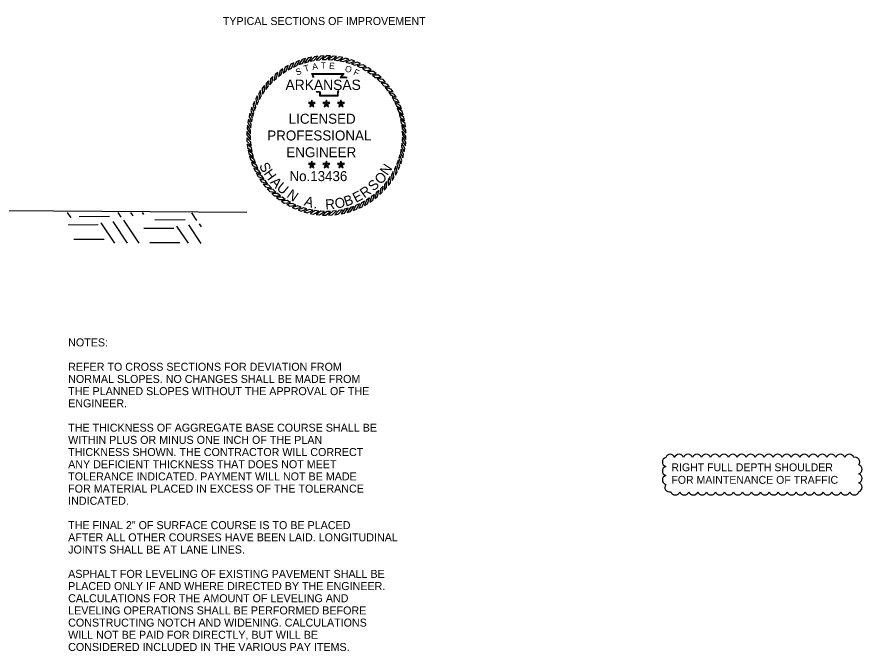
# Model space of a CAD drawing. Extents: x 1398183 to 1398373, y 1967240 to 1968889.
# Drawn here: x 1398305.8 to 1398369.1, y 1967753.9 to 1967801.4 of the extents above; entities that cross this region are included whole.
import ezdxf

# ---------------------------------------------------------------- set-up
doc = ezdxf.new("R2010")
doc.units = 0
for name, color, linetype in [('1', 7, 'Continuous'), ('19', 7, 'Continuous'), ('42', 7, 'Continuous'), ('9', 7, 'Continuous'), ('G-ANNO-SYMB', 7, 'Continuous')]:
    doc.layers.add(name, color=color, linetype=linetype)

msp = doc.modelspace()

# ---------------------------------------------------------------- linework, layer by layer
at = {"layer": '19'}
msp.add_lwpolyline([(1398257.039, 1967783.694), (1398271.783, 1967778.793), (1398285.898, 1967784.503), (1398294.031, 1967786.983), (1398323.027, 1967786.767)], dxfattribs=at)
for centre, radius, start, end in [((1398354.74, 1967768.294), 0.352, 17.5, 162.5), ((1398355.41, 1967768.294), 0.352, 17.5, 162.5), ((1398356.081, 1967768.294), 0.352, 17.5, 162.5), ((1398356.752, 1967768.294), 0.352, 17.5, 162.5), ((1398357.422, 1967768.294), 0.352, 17.5, 162.5), ((1398358.093, 1967768.294), 0.352, 17.5, 162.5), ((1398358.764, 1967768.294), 0.352, 17.5, 162.5), ((1398359.434, 1967768.294), 0.352, 17.5, 162.5), ((1398360.105, 1967768.294), 0.352, 17.5, 162.5), ((1398360.776, 1967768.294), 0.352, 17.5, 162.5), ((1398361.446, 1967768.294), 0.352, 17.5, 162.5), ((1398362.117, 1967768.294), 0.352, 17.5, 162.5), ((1398362.788, 1967768.294), 0.352, 17.5, 162.5), ((1398363.459, 1967768.294), 0.352, 17.5, 162.5), ((1398364.129, 1967768.294), 0.352, 17.5, 162.5), ((1398364.8, 1967768.294), 0.352, 17.5, 162.5), ((1398365.471, 1967768.294), 0.352, 17.5, 162.5), ((1398366.141, 1967768.294), 0.352, 17.5, 162.5), ((1398366.812, 1967768.294), 0.352, 17.5, 162.5), ((1398367.483, 1967768.294), 0.352, 17.5, 162.5), ((1398368.153, 1967768.294), 0.352, 17.5, 162.5), ((1398354.51, 1967768.065), 0.352, 107.5, 252.5), ((1398368.594, 1967768.065), 0.351, 322.43874, 107.43874), ((1398354.51, 1967767.394), 0.352, 107.5, 252.5), ((1398368.767, 1967767.515), 0.352, 287.5, 72.5), ((1398354.51, 1967766.723), 0.352, 107.5, 252.5), ((1398368.767, 1967766.845), 0.352, 287.5, 72.5), ((1398354.683, 1967766.174), 0.351, 142.43874, 287.43874), ((1398368.767, 1967766.174), 0.352, 287.5, 72.5), ((1398355.123, 1967765.944), 0.352, 197.5, 342.5), ((1398355.794, 1967765.944), 0.352, 197.5, 342.5), ((1398356.465, 1967765.944), 0.352, 197.5, 342.5), ((1398357.136, 1967765.944), 0.352, 197.5, 342.5), ((1398357.806, 1967765.944), 0.352, 197.5, 342.5), ((1398358.477, 1967765.944), 0.352, 197.5, 342.5), ((1398359.148, 1967765.944), 0.352, 197.5, 342.5), ((1398359.818, 1967765.944), 0.352, 197.5, 342.5), ((1398360.489, 1967765.944), 0.352, 197.5, 342.5), ((1398361.16, 1967765.944), 0.352, 197.5, 342.5), ((1398361.83, 1967765.944), 0.352, 197.5, 342.5), ((1398362.501, 1967765.944), 0.352, 197.5, 342.5), ((1398363.172, 1967765.944), 0.352, 197.5, 342.5), ((1398363.842, 1967765.944), 0.352, 197.5, 342.5), ((1398364.513, 1967765.944), 0.352, 197.5, 342.5), ((1398365.184, 1967765.944), 0.352, 197.5, 342.5), ((1398365.854, 1967765.944), 0.352, 197.5, 342.5), ((1398366.525, 1967765.944), 0.352, 197.5, 342.5), ((1398367.196, 1967765.944), 0.352, 197.5, 342.5), ((1398367.867, 1967765.944), 0.352, 197.5, 342.5), ((1398368.537, 1967765.944), 0.352, 197.5, 342.5)]:
    msp.add_arc(centre, radius, start, end, dxfattribs=at)
at = {"layer": '9'}
for p, q in [((1398309.849, 1967786.357), (1398309.583, 1967786.753)), ((1398312.723, 1967786.445), (1398310.461, 1967786.43)), ((1398313.613, 1967786.406), (1398313.384, 1967786.746)), ((1398314.503, 1967786.497), (1398314.337, 1967786.744)), ((1398315.3, 1967786.588), (1398315.197, 1967786.742)), ((1398319.286, 1967786.155), (1398318.895, 1967786.736)), ((1398311.887, 1967785.816), (1398309.625, 1967785.801)), ((1398313.139, 1967784.452), (1398312.11, 1967785.982)), ((1398314.091, 1967784.45), (1398313, 1967786.073)), ((1398314.951, 1967784.449), (1398313.798, 1967786.165)), ((1398318.396, 1967786.193), (1398316.134, 1967786.179)), ((1398318.649, 1967784.442), (1398317.783, 1967785.731)), ((1398319.602, 1967784.44), (1398318.673, 1967785.822)), ((1398319.625, 1967785.683), (1398319.47, 1967785.913)), ((1398317.56, 1967785.564), (1398315.298, 1967785.55)), ((1398312.33, 1967784.739), (1398310.068, 1967784.725)), ((1398318.003, 1967784.488), (1398315.741, 1967784.473))]:
    msp.add_line(p, q, dxfattribs=at)
at = {"layer": 'G-ANNO-SYMB'}
for points in [[(1398327.879, 1967798.381), (1398327.628, 1967798.329), (1398327.343, 1967797.971), (1398327.61, 1967798.044)], [(1398328.342, 1967798.45), (1398328.088, 1967798.417), (1398327.776, 1967798.082), (1398328.048, 1967798.134)], [(1398328.81, 1967798.481), (1398328.553, 1967798.469), (1398328.216, 1967798.16), (1398328.492, 1967798.19)], [(1398329.278, 1967798.476), (1398329.021, 1967798.484), (1398328.661, 1967798.202), (1398328.938, 1967798.211)], [(1398329.745, 1967798.435), (1398329.489, 1967798.462), (1398329.108, 1967798.21), (1398329.385, 1967798.197)], [(1398330.206, 1967798.356), (1398329.954, 1967798.404), (1398329.554, 1967798.182), (1398329.829, 1967798.147)], [(1398330.661, 1967798.242), (1398330.413, 1967798.309), (1398329.997, 1967798.12), (1398330.268, 1967798.063)], [(1398326.121, 1967797.754), (1398325.898, 1967797.626), (1398325.738, 1967797.198), (1398325.97, 1967797.35)], [(1398326.54, 1967797.962), (1398326.309, 1967797.852), (1398326.115, 1967797.438), (1398326.358, 1967797.571)], [(1398326.975, 1967798.137), (1398326.735, 1967798.045), (1398326.51, 1967797.647), (1398326.763, 1967797.762)], [(1398327.422, 1967798.277), (1398327.176, 1967798.205), (1398326.92, 1967797.825), (1398327.181, 1967797.919)], [(1398331.105, 1967798.093), (1398330.863, 1967798.179), (1398330.433, 1967798.022), (1398330.699, 1967797.945)], [(1398331.535, 1967797.909), (1398331.301, 1967798.014), (1398330.861, 1967797.891), (1398331.12, 1967797.794)], [(1398331.951, 1967797.692), (1398331.725, 1967797.815), (1398331.277, 1967797.727), (1398331.527, 1967797.609)], [(1398325.337, 1967797.242), (1398325.137, 1967797.081), (1398325.046, 1967796.633), (1398325.251, 1967796.82)], [(1398325.719, 1967797.514), (1398325.507, 1967797.369), (1398325.381, 1967796.929), (1398325.6, 1967797.099)], [(1398332.347, 1967797.443), (1398332.132, 1967797.583), (1398331.678, 1967797.531), (1398331.919, 1967797.394)], [(1398332.723, 1967797.163), (1398332.52, 1967797.32), (1398332.063, 1967797.304), (1398332.292, 1967797.148)], [(1398333.076, 1967796.855), (1398332.886, 1967797.027), (1398332.429, 1967797.047), (1398332.646, 1967796.874)], [(1398324.643, 1967796.614), (1398324.471, 1967796.424), (1398324.451, 1967795.967), (1398324.624, 1967796.183)], [(1398324.977, 1967796.942), (1398324.791, 1967796.766), (1398324.735, 1967796.312), (1398324.925, 1967796.514)], [(1398333.404, 1967796.521), (1398333.228, 1967796.707), (1398332.774, 1967796.763), (1398332.976, 1967796.573)], [(1398333.704, 1967796.161), (1398333.543, 1967796.361), (1398333.095, 1967796.452), (1398333.282, 1967796.247)], [(1398324.055, 1967795.885), (1398323.915, 1967795.67), (1398323.967, 1967795.216), (1398324.104, 1967795.457)], [(1398324.335, 1967796.261), (1398324.178, 1967796.058), (1398324.194, 1967795.601), (1398324.35, 1967795.83)], [(1398333.976, 1967795.779), (1398333.831, 1967795.991), (1398333.391, 1967796.117), (1398333.561, 1967795.898)], [(1398334.216, 1967795.377), (1398334.088, 1967795.6), (1398333.66, 1967795.76), (1398333.812, 1967795.528)], [(1398323.806, 1967795.488), (1398323.683, 1967795.263), (1398323.771, 1967794.814), (1398323.888, 1967795.065)], [(1398327.889, 1967794.894), (1398327.95, 1967794.978), (1398327.889, 1967795.166), (1398327.828, 1967794.978)], [(1398328.98, 1967794.894), (1398329.041, 1967794.978), (1398328.98, 1967795.166), (1398328.919, 1967794.978)], [(1398330.071, 1967794.894), (1398330.132, 1967794.978), (1398330.071, 1967795.166), (1398330.01, 1967794.978)], [(1398334.424, 1967794.958), (1398334.314, 1967795.189), (1398333.9, 1967795.383), (1398334.034, 1967795.14)], [(1398323.405, 1967794.642), (1398323.319, 1967794.401), (1398323.475, 1967793.971), (1398323.553, 1967794.237)], [(1398323.589, 1967795.073), (1398323.484, 1967794.839), (1398323.606, 1967794.399), (1398323.704, 1967794.658)], [(1398327.889, 1967794.894), (1398327.828, 1967794.978), (1398327.63, 1967794.978), (1398327.79, 1967794.861)], [(1398327.889, 1967794.894), (1398327.79, 1967794.861), (1398327.729, 1967794.673), (1398327.889, 1967794.789)], [(1398327.889, 1967794.894), (1398327.988, 1967794.861), (1398328.148, 1967794.978), (1398327.95, 1967794.978)], [(1398327.889, 1967794.894), (1398327.889, 1967794.789), (1398328.049, 1967794.673), (1398327.988, 1967794.861)], [(1398328.98, 1967794.894), (1398328.919, 1967794.978), (1398328.721, 1967794.978), (1398328.881, 1967794.861)], [(1398328.98, 1967794.894), (1398328.881, 1967794.861), (1398328.82, 1967794.673), (1398328.98, 1967794.789)], [(1398328.98, 1967794.894), (1398329.079, 1967794.861), (1398329.239, 1967794.978), (1398329.041, 1967794.978)], [(1398328.98, 1967794.894), (1398328.98, 1967794.789), (1398329.14, 1967794.673), (1398329.079, 1967794.861)], [(1398330.071, 1967794.894), (1398330.01, 1967794.978), (1398329.812, 1967794.978), (1398329.972, 1967794.861)], [(1398330.071, 1967794.894), (1398329.972, 1967794.861), (1398329.911, 1967794.673), (1398330.071, 1967794.789)], [(1398330.071, 1967794.894), (1398330.17, 1967794.861), (1398330.33, 1967794.978), (1398330.132, 1967794.978)], [(1398330.071, 1967794.894), (1398330.071, 1967794.789), (1398330.231, 1967794.673), (1398330.17, 1967794.861)], [(1398334.599, 1967794.523), (1398334.508, 1967794.763), (1398334.11, 1967794.988), (1398334.224, 1967794.735)], [(1398334.739, 1967794.076), (1398334.667, 1967794.322), (1398334.288, 1967794.578), (1398334.382, 1967794.317)], [(1398323.256, 1967794.199), (1398323.189, 1967793.951), (1398323.378, 1967793.535), (1398323.434, 1967793.806)], [(1398334.843, 1967793.619), (1398334.791, 1967793.87), (1398334.433, 1967794.155), (1398334.506, 1967793.888)], [(1398323.063, 1967793.282), (1398323.036, 1967793.027), (1398323.288, 1967792.646), (1398323.301, 1967792.923)], [(1398323.141, 1967793.744), (1398323.094, 1967793.492), (1398323.316, 1967793.092), (1398323.35, 1967793.367)], [(1398334.912, 1967793.156), (1398334.879, 1967793.41), (1398334.544, 1967793.722), (1398334.596, 1967793.45)], [(1398334.944, 1967792.688), (1398334.931, 1967792.945), (1398334.622, 1967793.282), (1398334.652, 1967793.006)], [(1398323.022, 1967792.816), (1398323.014, 1967792.559), (1398323.296, 1967792.199), (1398323.287, 1967792.476)], [(1398334.939, 1967792.22), (1398334.946, 1967792.476), (1398334.664, 1967792.837), (1398334.673, 1967792.56)], [(1398323.017, 1967792.347), (1398323.029, 1967792.091), (1398323.338, 1967791.754), (1398323.308, 1967792.029)], [(1398334.897, 1967791.753), (1398334.924, 1967792.008), (1398334.672, 1967792.39), (1398334.659, 1967792.113)], [(1398323.048, 1967791.88), (1398323.081, 1967791.626), (1398323.416, 1967791.314), (1398323.364, 1967791.586)], [(1398323.117, 1967791.417), (1398323.169, 1967791.166), (1398323.527, 1967790.881), (1398323.454, 1967791.148)], [(1398334.704, 1967790.837), (1398334.771, 1967791.085), (1398334.582, 1967791.501), (1398334.526, 1967791.23)], [(1398334.819, 1967791.292), (1398334.866, 1967791.544), (1398334.644, 1967791.944), (1398334.61, 1967791.669)], [(1398323.221, 1967790.96), (1398323.293, 1967790.714), (1398323.672, 1967790.458), (1398323.579, 1967790.719)], [(1398334.555, 1967790.393), (1398334.641, 1967790.635), (1398334.485, 1967791.065), (1398334.407, 1967790.798)], [(1398323.361, 1967790.513), (1398323.452, 1967790.273), (1398323.85, 1967790.048), (1398323.736, 1967790.301)], [(1398323.536, 1967790.078), (1398323.646, 1967789.846), (1398324.06, 1967789.653), (1398323.926, 1967789.896)], [(1398327.889, 1967790.325), (1398327.828, 1967790.41), (1398327.63, 1967790.41), (1398327.79, 1967790.293)], [(1398327.889, 1967790.325), (1398327.79, 1967790.293), (1398327.729, 1967790.105), (1398327.889, 1967790.221)], [(1398327.889, 1967790.325), (1398327.95, 1967790.41), (1398327.889, 1967790.598), (1398327.828, 1967790.41)], [(1398327.889, 1967790.325), (1398327.988, 1967790.293), (1398328.148, 1967790.41), (1398327.95, 1967790.41)], [(1398327.889, 1967790.325), (1398327.889, 1967790.221), (1398328.049, 1967790.105), (1398327.988, 1967790.293)], [(1398328.98, 1967790.325), (1398328.919, 1967790.41), (1398328.721, 1967790.41), (1398328.881, 1967790.293)], [(1398328.98, 1967790.325), (1398328.881, 1967790.293), (1398328.82, 1967790.105), (1398328.98, 1967790.221)], [(1398328.98, 1967790.325), (1398329.041, 1967790.41), (1398328.98, 1967790.598), (1398328.919, 1967790.41)], [(1398328.98, 1967790.325), (1398329.079, 1967790.293), (1398329.239, 1967790.41), (1398329.041, 1967790.41)], [(1398328.98, 1967790.325), (1398328.98, 1967790.221), (1398329.14, 1967790.105), (1398329.079, 1967790.293)], [(1398330.071, 1967790.325), (1398330.01, 1967790.41), (1398329.812, 1967790.41), (1398329.972, 1967790.293)], [(1398330.071, 1967790.325), (1398329.972, 1967790.293), (1398329.911, 1967790.105), (1398330.071, 1967790.221)], [(1398330.071, 1967790.325), (1398330.132, 1967790.41), (1398330.071, 1967790.598), (1398330.01, 1967790.41)], [(1398330.071, 1967790.325), (1398330.17, 1967790.293), (1398330.33, 1967790.41), (1398330.132, 1967790.41)], [(1398330.071, 1967790.325), (1398330.071, 1967790.221), (1398330.231, 1967790.105), (1398330.17, 1967790.293)], [(1398334.154, 1967789.547), (1398334.277, 1967789.773), (1398334.19, 1967790.221), (1398334.072, 1967789.971)], [(1398334.371, 1967789.962), (1398334.476, 1967790.197), (1398334.354, 1967790.637), (1398334.256, 1967790.378)], [(1398323.744, 1967789.659), (1398323.872, 1967789.436), (1398324.3, 1967789.276), (1398324.148, 1967789.508)], [(1398333.625, 1967788.775), (1398333.782, 1967788.978), (1398333.766, 1967789.435), (1398333.61, 1967789.205)], [(1398333.905, 1967789.151), (1398334.045, 1967789.365), (1398333.993, 1967789.82), (1398333.856, 1967789.579)], [(1398323.984, 1967789.257), (1398324.129, 1967789.045), (1398324.569, 1967788.919), (1398324.399, 1967789.138)], [(1398324.256, 1967788.875), (1398324.417, 1967788.675), (1398324.865, 1967788.584), (1398324.678, 1967788.789)], [(1398333.317, 1967788.422), (1398333.49, 1967788.612), (1398333.509, 1967789.069), (1398333.336, 1967788.852)], [(1398324.556, 1967788.515), (1398324.732, 1967788.329), (1398325.186, 1967788.273), (1398324.984, 1967788.463)], [(1398324.884, 1967788.18), (1398325.074, 1967788.008), (1398325.531, 1967787.988), (1398325.314, 1967788.162)], [(1398332.623, 1967787.794), (1398332.823, 1967787.955), (1398332.914, 1967788.403), (1398332.709, 1967788.216)], [(1398332.983, 1967788.094), (1398333.169, 1967788.27), (1398333.225, 1967788.724), (1398333.035, 1967788.522)], [(1398325.237, 1967787.872), (1398325.44, 1967787.716), (1398325.897, 1967787.732), (1398325.668, 1967787.888)], [(1398325.613, 1967787.593), (1398325.828, 1967787.453), (1398326.282, 1967787.505), (1398326.041, 1967787.642)], [(1398331.42, 1967787.074), (1398331.651, 1967787.183), (1398331.845, 1967787.598), (1398331.602, 1967787.464)], [(1398331.839, 1967787.282), (1398332.062, 1967787.41), (1398332.222, 1967787.838), (1398331.99, 1967787.686)], [(1398332.241, 1967787.522), (1398332.453, 1967787.667), (1398332.579, 1967788.107), (1398332.36, 1967787.937)], [(1398326.009, 1967787.344), (1398326.235, 1967787.221), (1398326.684, 1967787.308), (1398326.433, 1967787.426)], [(1398326.425, 1967787.127), (1398326.659, 1967787.022), (1398327.099, 1967787.144), (1398326.84, 1967787.242)], [(1398326.855, 1967786.943), (1398327.097, 1967786.857), (1398327.527, 1967787.013), (1398327.261, 1967787.091)], [(1398327.299, 1967786.794), (1398327.547, 1967786.727), (1398327.963, 1967786.916), (1398327.692, 1967786.972)], [(1398329.618, 1967786.586), (1398329.872, 1967786.619), (1398330.184, 1967786.953), (1398329.912, 1967786.901)], [(1398330.081, 1967786.654), (1398330.332, 1967786.707), (1398330.617, 1967787.065), (1398330.35, 1967786.992)], [(1398330.538, 1967786.759), (1398330.784, 1967786.831), (1398331.04, 1967787.21), (1398330.779, 1967787.116)], [(1398330.985, 1967786.899), (1398331.225, 1967786.99), (1398331.45, 1967787.388), (1398331.197, 1967787.274)], [(1398327.754, 1967786.679), (1398328.006, 1967786.632), (1398328.406, 1967786.854), (1398328.131, 1967786.888)], [(1398328.216, 1967786.601), (1398328.471, 1967786.574), (1398328.852, 1967786.826), (1398328.575, 1967786.839)], [(1398328.682, 1967786.559), (1398328.939, 1967786.552), (1398329.299, 1967786.834), (1398329.022, 1967786.825)], [(1398329.151, 1967786.554), (1398329.407, 1967786.567), (1398329.744, 1967786.876), (1398329.468, 1967786.846)]]:
    msp.add_lwpolyline(points, close=True, dxfattribs=at)
for points in [[(1398328.024, 1967796.848), (1398327.885, 1967797.149), (1398330.292, 1967797.15), (1398330.09, 1967796.898), (1398330.254, 1967796.9), (1398330.391, 1967796.902), (1398330.527, 1967796.887)], [(1398328.059, 1967796.864), (1398327.945, 1967797.111), (1398330.212, 1967797.112), (1398330.011, 1967796.859), (1398330.254, 1967796.862), (1398330.389, 1967796.864), (1398330.523, 1967796.849)], [(1398329.912, 1967795.839), (1398329.871, 1967795.806), (1398329.858, 1967795.756), (1398329.844, 1967795.631), (1398329.844, 1967795.465), (1398328.501, 1967795.465), (1398328.501, 1967795.69), (1398328.501, 1967795.74), (1398328.446, 1967795.756), (1398328.255, 1967795.756), (1398328.221, 1967795.808)], [(1398329.888, 1967795.869), (1398329.838, 1967795.828), (1398329.82, 1967795.763), (1398329.806, 1967795.633), (1398329.806, 1967795.503), (1398328.539, 1967795.503), (1398328.539, 1967795.69), (1398328.539, 1967795.768), (1398328.452, 1967795.794), (1398328.276, 1967795.794), (1398328.253, 1967795.829)]]:
    msp.add_lwpolyline(points, dxfattribs=at)

# ---------------------------------------------------------------- texts
at = {"layer": '1'}
msp.add_text('TYPICAL SECTIONS OF IMPROVEMENT', height=0.6, dxfattribs=at).set_placement((1398321.219, 1967800.791))
at = {"layer": '19'}
for s, p in [('NOTES:', (1398309.634, 1967776.72)), ('REFER TO CROSS SECTIONS FOR DEVIATION FROM', (1398309.634, 1967774.895)), ('NORMAL SLOPES. NO CHANGES SHALL BE MADE FROM ', (1398309.634, 1967773.983)), ('THE PLANNED SLOPES WITHOUT THE APPROVAL OF THE', (1398309.634, 1967773.07)), ('ENGINEER.', (1398309.634, 1967772.158)), ('THE THICKNESS OF AGGREGATE BASE COURSE SHALL BE', (1398309.634, 1967770.333)), ('WITHIN PLUS OR MINUS ONE INCH OF THE PLAN ', (1398309.634, 1967769.42)), ('THICKNESS SHOWN. THE CONTRACTOR WILL CORRECT', (1398309.634, 1967768.508)), ('ANY DEFICIENT THICKNESS THAT DOES NOT MEET', (1398309.634, 1967767.595)), ('TOLERANCE INDICATED. PAYMENT WILL NOT BE MADE', (1398309.634, 1967766.683)), ('FOR MATERIAL PLACED IN EXCESS OF THE TOLERANCE', (1398309.634, 1967765.77)), ('INDICATED.', (1398309.634, 1967764.858)), ('THE FINAL 2" OF SURFACE COURSE IS TO BE PLACED', (1398309.634, 1967763.033)), ('AFTER ALL OTHER COURSES HAVE BEEN LAID. LONGITUDINAL', (1398309.634, 1967762.12)), ('JOINTS SHALL BE AT LANE LINES.', (1398309.634, 1967761.208)), ('ASPHALT FOR LEVELING OF EXISTING PAVEMENT SHALL BE', (1398309.634, 1967759.383)), ('PLACED ONLY IF AND WHERE DIRECTED BY THE ENGINEER.', (1398309.634, 1967758.47)), ('CALCULATIONS FOR THE AMOUNT OF LEVELING AND', (1398309.634, 1967757.558)), ('LEVELING OPERATIONS SHALL BE PERFORMED BEFORE ', (1398309.634, 1967756.645)), ('CONSTRUCTING NOTCH AND WIDENING. CALCULATIONS', (1398309.634, 1967755.733)), ('WILL NOT BE PAID FOR DIRECTLY, BUT WILL BE', (1398309.634, 1967754.82)), ('CONSIDERED INCLUDED IN THE VARIOUS PAY ITEMS.', (1398309.634, 1967753.908))]:
    msp.add_text(s, height=0.6, dxfattribs=at).set_placement(p)
at = {"layer": '42'}
for s, p in [('RIGHT FULL DEPTH SHOULDER', (1398354.831, 1967767.371)), ('FOR MAINTENANCE OF TRAFFIC', (1398354.831, 1967766.431))]:
    msp.add_text(s, height=0.59001, rotation=360, dxfattribs=at).set_placement(p)
at = {"layer": 'G-ANNO-SYMB'}
for s, height, rotation, p in [('T', 0.475, 16.90148, (1398327.375, 1967797.277)), ('A', 0.475, 8.67877, (1398327.951, 1967797.427)), ('T', 0.475, 1.47887, (1398328.564, 1967797.522)), ('E', 0.475, 356.67203, (1398329.171, 1967797.507)), ('O', 0.475, 341.2218, (1398330.324, 1967797.344)), ('S', 0.475, 19.77256, (1398326.771, 1967797.006)), ('F', 0.475, 335.36282, (1398330.964, 1967797.094)), ('S', 0.75, 298.16364, (1398323.912, 1967790.258)), ('N', 0.75, 56.10067, (1398333.554, 1967789.474)), ('H', 0.75, 305.61905, (1398324.254, 1967789.67)), ('O', 0.75, 44.77573, (1398333.033, 1967788.799)), ('A', 0.75, 313.44722, (1398324.73, 1967788.986)), ('U', 0.75, 320.90262, (1398325.198, 1967788.497)), ('S', 0.75, 43.48784, (1398332.518, 1967788.302)), ('N', 0.75, 324.93262, (1398325.954, 1967787.938)), ('E', 0.75, 27.83149, (1398331.194, 1967787.46)), ('R', 0.75, 35.65967, (1398331.828, 1967787.792)), ('A', 0.75, 343.09908, (1398327.261, 1967787.295)), ('R', 0.75, 3.22866, (1398328.918, 1967786.981)), ('O', 0.75, 11.42961, (1398329.685, 1967787.03)), ('B', 0.75, 18.88501, (1398330.437, 1967787.189)), ('.', 0.75, 351.30002, (1398327.998, 1967787.076))]:
    msp.add_text(s, height=height, rotation=rotation, dxfattribs=at).set_placement(p)
for s, height, p in [('ARKANSAS', 0.7747, (1398325.918, 1967795.926)), ('LICENSED', 0.75, (1398326.159, 1967793.397)), ('PROFESSIONAL', 0.75, (1398324.551, 1967792.143)), ('ENGINEER', 0.75, (1398325.98, 1967790.889)), ('No.13436', 0.747, (1398326.217, 1967789.101))]:
    msp.add_text(s, height=height, dxfattribs=at).set_placement(p)

doc.saveas('drawing.dxf')
